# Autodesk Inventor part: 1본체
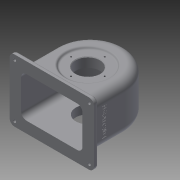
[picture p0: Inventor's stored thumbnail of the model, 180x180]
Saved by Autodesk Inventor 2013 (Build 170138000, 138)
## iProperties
Created: 2016-01
Part Number: 1본체
Material: Generic
Document SubType Name: Modeling
Designer: Administrator
Density: 1 g/cm^3
Author: Administrator
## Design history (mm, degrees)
sketch "스케치1"
  geometry: L1 (-57, 0)-(-57, -64); L2 (57, 0)-(57, -64); L3 (-57, -64)-(57, -64); A1 r 57 centre (0, 0) between (57, 0) and (-57, 0); 1 further point
  constraints: 6 end point, 2 point on circle, 2 tangent, 1 centre point, 1 coincident, 1 parallel, 1 perpendicular, 1 vertical
  dimensions: "d0" = 114 diameter of A1; "d1" = 64 distance from line of L3 point (0, 0)
extrude "돌출1" new body sketch "스케치1" distance "d2" = 77; taper "d3" = 0 deg
sketch "스케치2"
  geometry: L1 (0, 0)-(114, 0) reference; L2 (114, 0)-(114, 77) reference; L3 (0, 77)-(114, 77) reference; L4 (0, 0)-(0, 77) reference; L5 (-13, -13.5)-(127, -13.5); L6 (127, -13.5)-(127, 90.5); L7 (127, 90.5)-(-13, 90.5); L8 (-13, 90.5)-(-13, -13.5); L9 (0, 38.5)-(114, 38.5); L10 (57, 0)-(57, 77)
  constraints: 12 end point, 3 midpoint, 2 parallel, 1 horizontal, 1 perpendicular
  dimensions: "d4" = 70 distance between parallel lines of L10 L8; "d6" = 140 distance between parallel lines of L6 L8; "d7" = 52 distance between parallel lines of L9 L7; "d8" = 104 distance between parallel lines of L5 L7
extrude "돌출2" join sketch "스케치2" distance "d9" = 7; taper "d10" = 0 deg
node "작업 평면1"
sketch "스케치3"
  geometry: L1 (19, 64)-(19, 0); L2 (121, 64)-(121, 0); L3 (19, 0)-(121, 0); L4 (0, 0)-(140, 0) reference; A1 r 51 centre (70, 64) between (121, 64) and (19, 64); 1 further point
  constraints: 6 end point, 2 point on circle, 2 tangent, 1 centre point, 1 coincident, 1 collinear, 1 parallel, 1 perpendicular, 1 point on line, 1 vertical
  dimensions: "d11" = 102 diameter of A1
extrude "돌출3" cut sketch "스케치3" stored distance "d12" = 67; taper "d13" = 0 deg
sketch "스케치4"
  geometry: L1 (-4, 77)-(-4, 58); L2 (-64, 90.5)-(-64, -13.5) reference; L3 (51, 72)-(0, 72) reference; L4 (57, 77)-(0, 77) reference; L5 (0, 72)-(-64, 72) reference; L6 (0, 77)-(-57, 77) reference; L7 (37.426, 74)-(-4, 74); L8 (24, 58)-(-4, 58); L9 (24, 58)-(37.426, 74); 1 further point
  constraints: 8 end point, 2 point on line, 1 parallel, 1 vertical
  dimensions: "d14" = 60 distance between parallel lines of L2 L1; "d16" = 3 distance between parallel lines of L6 L7; "d17" = 16 distance between parallel lines of L7 L8; "d20" = 28 distance of L8.start L1.end; "d21" = 50 deg angle of L8 L9
revolve "회전1" sketch "스케치4" stored, may be unused: angle "d22" = 90 deg
node "작업 평면2"
sketch "스케치8"
  geometry: L1 (140, 104)-(140, 0) reference; L2 (0, 104)-(140, 104) reference; L3 (70, 104)-(70, 25.33); L4 (140, 52)-(7.319, 52); C1 r 6 at (70, 52); 1 further point
  constraints: 4 end point, 2 midpoint, 2 perpendicular, 2 point on line, 1 centre point
  dimensions: "d33" = 12 diameter of C1
extrude "돌출6" join sketch "스케치8" stored distance "d34" = 10; taper "d35" = 0 deg
sketch "스케치9"
  geometry: L1 (0, 0)-(0, -77) reference; L2 (-13, 13.5)-(-13, -90.5) reference; L3 (127, -90.5)-(127, 13.5) reference; L4 (-5, 21.847)-(-5, -103.111); L5 (-31.881, 5.5)-(14.035, 5.5); L6 (0, -38.5)-(14.035, -38.5); C1 r 2.5 at (-5, 5.5); 1 further point
  constraints: 6 end point, 2 parallel, 2 point on line, 1 centre point, 1 midpoint, 1 perpendicular
  dimensions: "d36" = 8 distance between parallel lines of L2 L4; "d37" = 44 distance between parallel lines of L6 L5; "d38" = 5 diameter of C1
extrude "돌출7" cut sketch "스케치9" distance "d39" = 10; taper "d40" = 0 deg
sketch "스케치10"
  geometry: L1 (0, 0)-(0, -77) reference; L2 (127, -90.5)-(127, 13.5) reference; L3 (0, -38.5)-(-24.213, -38.5); C1 r 2.5 at (-5, 5.5) reference; C2 r 2.5 at (-5, -38.5); 1 further point
  constraints: 2 end point, 1 centre point, 1 midpoint, 1 perpendicular, 1 point on line, 1 vertical alignment
  dimensions: "d41" = 5 diameter of C2
extrude "돌출8" cut sketch "스케치10" distance "d42" = 10; taper "d43" = 0 deg
node "작업 평면3"
sketch "스케치12"
  geometry: C1 r 28 at (0, 0) reference; C2 r 20 at (0, 0); 1 further point
  constraints: 1 centre point, 1 coincident
  dimensions: "d45" = 40 diameter of C2
extrude "돌출9" cut sketch "스케치12" stored distance "d46" = 10; taper "d47" = 0 deg
sketch "스케치13"
  geometry: L1 (90.5, 97.416)-(87.5, 94.899); L2 (85.5, 64)-(18.5, 64) reference; L3 (18.5, 64)-(18.5, 64) reference; L4 (18.5, 64)-(85.5, 64) reference; L5 (85.5, 64)-(85.5, 64) reference; L6 (85.5, 99.747)-(71.5, 88) reference; L7 (87.5, 94.899)-(87.5, 60); L8 (90.5, 80)-(90.5, 40) reference; L9 (90.5, 97.416)-(90.5, 60); L10 (87.5, 60)-(90.5, 60); L11 (104, 0)-(0, 0) reference; 1 further point
  constraints: 8 end point, 2 perpendicular, 1 parallel, 1 point on line
  dimensions: "d48" = 5 distance between parallel lines of L1 L6; "d49" = 3 distance between parallel lines of L8 L7; "d50" = 60 distance between parallel lines of L11 L10
revolve "회전3" sketch "스케치13" stored, may be unused: angle "d51" = 90 deg
sketch "스케치14"
  geometry: C1 r 20 at (0, -4) reference; C2 r 31 at (0, -4)
  constraints: 1 centre point, 1 coincident
  dimensions: "d52" = 62 diameter of C2
extrude "돌출10" join sketch "스케치14" distance "d53" = 10; taper "d54" = 0 deg
sketch "스케치15" dims "d55" = 56
  geometry: L1 (0, 0)-(0, 39.671); C1 r 34.899 at (0, 0) reference; 3 further points
  constraints: 2 end point, 1 coincident, 1 point on line, 1 vertical, 1 vertical alignment, 2 other
hole "구멍1" sketch "스케치15" at (0, 28) diameter "d56" = 2.459; stored, may be unused: countersink angle "d60" = 90 deg, drill point angle "d62" = 118 deg; dims "d57" = 7, "d58" = 4, "d59" = 2, "d61" = 9
sketch "스케치16" dims "d66" = 48
  geometry: L1 (0, 0)-(0, 47.578); C1 r 31 at (0, 0) reference; 3 further points
  constraints: 2 end point, 1 coincident, 1 point on line, 1 vertical, 1 vertical alignment, 2 other
hole "구멍2" sketch "스케치16" at (0, 24) diameter "d67" = 2.459; stored, may be unused: countersink angle "d71" = 90 deg, drill point angle "d73" = 118 deg; dims "d68" = 6, "d69" = 4, "d70" = 2, "d72" = 8
sketch "스케치17"
  geometry: C1 r 6 at (0, 0) reference; 2 further points
  constraints: 1 coincident
hole "구멍3" sketch "스케치17" at (0, 0) diameter "d77" = 4.459; stored, may be unused: countersink angle "d81" = 90 deg, drill point angle "d83" = 118 deg; dims "d78" = 19, "d79" = 4, "d80" = 2, "d82" = 20
fillet "모깎기1" dims "d84" = 9
fillet "모깎기2" dims "d85" = 14
fillet "모깎기3" dims "d86" = 8
chamfer "모따기1" distance "d87" = 1; stored, may be unused: second distance "d88" = 2, angle "d89" = 45 deg
fillet "모깎기4" dims "d90" = 3
fillet "모깎기5" dims "d91" = 1
sketch "스케치18"
  geometry: L1 (-14, 0)-(-14, -56) reference; L2 (68.5, -64)-(-19.5, -64) reference; 2 further points
  constraints: 1 other
  dimensions: "d92" = 38.5 distance from line of L1 point (24.5, -34); "d93" = 30 distance from line of L2 point (24.5, -34)
feature "엠보싱1" sketch "스케치18" dims "d0" = 114, "d1" = 64, "d10" = 0, "d94" = 0.5, "d95" = 0
fillet "모깎기6" dims "d96" = 3
sketch "스케치20"
  geometry: C1 r 2.5 at (119, -38.5) reference; C2 r 2.5 at (-5, -38.5) reference; 1 further point
extrude "돌출12" join sketch "스케치20" distance "d100" = 7; taper "d101" = 0 deg
node "솔리드1"
mirror "대칭1"
mirror "대칭2"
pattern_circular "원형 패턴1" dims angle "d64" = 360 deg
pattern_circular "원형 패턴2" dims angle "d75" = 360 deg
node "투영된 루프1"
other parameters: "d32" = -127
